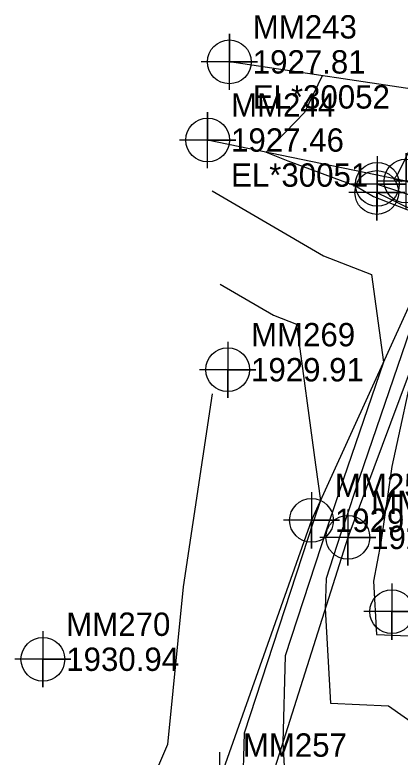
# Model space of a CAD drawing. Extents: x 1004378 to 1005103, y 553854 to 554288.
# Drawn here: x 1004938.6 to 1004979.8, y 554208.9 to 554288.4 of the extents above; entities that cross this region are included whole.
import ezdxf

# ---------------------------------------------------------------- set-up
doc = ezdxf.new("R2010")
doc.units = 0
for name, color, linetype in [('DTM Contours Major', 7, 'Continuous'), ('DTM Contours Minor', 7, 'Continuous'), ('Exist DTM Breakline', 7, 'Continuous'), ('Exist DTM Breakline Cogo Elevation', 7, 'Continuous'), ('Exist DTM Breakline Cogo Number', 7, 'Continuous'), ('Exist DTM Breakline Cogo Point CELL', 7, 'Continuous'), ('Exist DTM Regular Point CELL', 7, 'Continuous'), ('Exist DTM Regular Point Cogo Elevation', 7, 'Continuous'), ('Exist DTM Regular Point Cogo Number', 7, 'Continuous'), ('Exist Roads Soil', 7, 'Continuous'), ('Exist Roads Soil Cogo Comment', 7, 'Continuous'), ('Exist Roads Soil Cogo Elevation', 7, 'Continuous'), ('Exist Roads Soil Cogo Number', 7, 'Continuous'), ('Exist Roads Soil Cogo Point CELL', 7, 'Continuous')]:
    doc.layers.add(name, color=color, linetype=linetype)

msp = doc.modelspace()

# ---------------------------------------------------------------- linework, layer by layer
at = {"layer": 'DTM Contours Major'}
msp.add_lwpolyline([(1004959.718, 554247.837), (1004956.604, 554227.189), (1004954.914, 554210.3), (1004952.827, 554205.351), (1004957.486, 554203.505), (1004956.747, 554201.367), (1004957.928, 554197.612), (1004957.091, 554192.78), (1004956.399, 554184.65), (1004957.552, 554183.351), (1004960.987, 554182.443), (1004972.543, 554180.34), (1004973.586, 554164.908)], dxfattribs=at)
at = {"layer": 'DTM Contours Minor'}
for points in [[(1004971.499, 554281.9), (1004969.584, 554277.964), (1004965.483, 554273.724), (1004967.796, 554272.784), (1004975.049, 554270.111), (1004976.979, 554268.984), (1004983.286, 554266.522)], [(1004982.863, 554278.109), (1004979.529, 554271.254), (1004979.178, 554270.892), (1004979.965, 554270.572)], [(1004959.702, 554269.582), (1004971.624, 554262.617), (1004976.768, 554260.609), (1004978.047, 554251.242), (1004973.763, 554238.724), (1004972.987, 554236.396), (1004972.005, 554233.516), (1004967.53, 554219.799), (1004967.269, 554210.518), (1004967.445, 554207.322), (1004969.402, 554207.239), (1004978.487, 554200.785), (1004978.039, 554194.545), (1004976.925, 554192.516), (1004976.46, 554191.387), (1004975.325, 554186.125), (1004976.766, 554164.808), (1004977.29, 554160.519), (1004977.431, 554159.226), (1004977.764, 554154.77), (1004975.638, 554146.291), (1004977.602, 554126.359), (1004974.778, 554116.687)], [(1004984.509, 554265.252), (1004975.486, 554238.886), (1004973.8, 554233.83), (1004973.46, 554232.832), (1004971.91, 554228.081), (1004971.82, 554224.865), (1004972.377, 554214.703), (1004978.6, 554214.438), (1004982.901, 554211.383)], [(1004960.573, 554259.577), (1004966.268, 554256.25), (1004968.726, 554255.291), (1004970.783, 554240.224), (1004971.304, 554236.409), (1004970.551, 554234.199), (1004963.15, 554211.518), (1004962.971, 554205.136), (1004962.961, 554204.794), (1004962.243, 554202.716), (1004964.954, 554194.096), (1004969.359, 554191.452), (1004974.072, 554190.188), (1004973.609, 554188.041), (1004975.278, 554163.357), (1004975.678, 554160.081), (1004975.786, 554159.093), (1004976.151, 554154.202), (1004974.457, 554147.443), (1004976.568, 554126.021), (1004974.041, 554117.366)], [(1004981.55, 554252.068), (1004978.949, 554240.061), (1004977.774, 554231.939), (1004976.997, 554227.796), (1004977.31, 554222.084), (1004985.01, 554221.756)]]:
    msp.add_lwpolyline(points, dxfattribs=at)
at = {"layer": 'Exist DTM Breakline'}
for points in [[(1004977.38, 554270.285), (1004987.161, 554267.094), (1004974.231, 554232.47), (1004965.01, 554203.394)], [(1004977.332, 554269.403), (1004984.686, 554265.845), (1004970.343, 554234.297), (1004960.488, 554206.483)]]:
    msp.add_lwpolyline(points, dxfattribs=at)
at = {"layer": 'Exist DTM Breakline Cogo Point CELL'}
for points in [[(1004977.38, 554273.285), (1004977.38, 554267.285), (1004977.38, 554270.285), (1004980.38, 554270.285), (1004974.38, 554270.285)], [(1004977.332, 554272.403), (1004977.332, 554266.403), (1004977.332, 554269.403), (1004980.332, 554269.403), (1004974.332, 554269.403)], [(1004970.343, 554237.297), (1004970.343, 554231.297), (1004970.343, 554234.297), (1004973.343, 554234.297), (1004967.343, 554234.297)], [(1004974.231, 554235.47), (1004974.231, 554229.47), (1004974.231, 554232.47), (1004977.231, 554232.47), (1004971.231, 554232.47)], [(1004960.488, 554209.483), (1004960.488, 554203.483), (1004960.488, 554206.483), (1004963.488, 554206.483), (1004957.488, 554206.483)]]:
    msp.add_lwpolyline(points, dxfattribs=at)
for centre in [(1004977.38, 554270.285), (1004977.332, 554269.403), (1004970.343, 554234.297), (1004974.231, 554232.47)]:
    msp.add_circle(centre, 2.344, dxfattribs=at)
at = {"layer": 'Exist DTM Regular Point CELL'}
for points in [[(1004961.37, 554253.426), (1004961.37, 554247.426), (1004961.37, 554250.426), (1004964.37, 554250.426), (1004958.37, 554250.426)], [(1004978.936, 554227.517), (1004978.936, 554221.517), (1004978.936, 554224.517), (1004981.936, 554224.517), (1004975.936, 554224.517)], [(1004941.59, 554222.421), (1004941.59, 554216.421), (1004941.59, 554219.421), (1004944.59, 554219.421), (1004938.59, 554219.421)]]:
    msp.add_lwpolyline(points, dxfattribs=at)
for centre in [(1004961.37, 554250.426), (1004978.936, 554224.517), (1004941.59, 554219.421)]:
    msp.add_circle(centre, 2.344, dxfattribs=at)
at = {"layer": 'Exist Roads Soil'}
for points in [[(1005035.476, 554262.003), (1005019.749, 554266.277), (1004983.505, 554280.108), (1004961.55, 554283.385)], [(1005026.922, 554247.386), (1005013.881, 554254.375), (1004980.46, 554270.626), (1004959.228, 554275.018)]]:
    msp.add_lwpolyline(points, dxfattribs=at)
at = {"layer": 'Exist Roads Soil Cogo Point CELL'}
for points in [[(1004961.55, 554280.385), (1004961.55, 554286.385), (1004961.55, 554283.385), (1004964.55, 554283.385), (1004958.55, 554283.385)], [(1004959.228, 554272.018), (1004959.228, 554278.018), (1004959.228, 554275.018), (1004962.228, 554275.018), (1004956.228, 554275.018)], [(1004980.46, 554267.626), (1004980.46, 554273.626), (1004980.46, 554270.626), (1004983.46, 554270.626), (1004977.46, 554270.626)]]:
    msp.add_lwpolyline(points, dxfattribs=at)
for centre in [(1004961.55, 554283.385), (1004959.228, 554275.018), (1004980.46, 554270.626)]:
    msp.add_circle(centre, 2.344, dxfattribs=at)

# ---------------------------------------------------------------- texts
at = {"layer": 'Exist DTM Breakline Cogo Elevation'}
for s, p in [('1929.14', (1004972.843, 554233.047)), ('1926.47', (1004976.731, 554231.22))]:
    msp.add_text(s, height=2.5, dxfattribs=at).set_placement(p)
at = {"layer": 'Exist DTM Breakline Cogo Number'}
for s, p in [('MM254', (1004972.843, 554236.797)), ('MM252', (1004976.731, 554234.97)), ('MM257', (1004962.988, 554208.983))]:
    msp.add_text(s, height=2.5, dxfattribs=at).set_placement(p)
at = {"layer": 'Exist DTM Regular Point Cogo Elevation'}
for s, p in [('1929.91', (1004963.87, 554249.176)), ('1930.94', (1004944.09, 554218.171))]:
    msp.add_text(s, height=2.5, dxfattribs=at).set_placement(p)
at = {"layer": 'Exist DTM Regular Point Cogo Number'}
for s, p in [('MM269', (1004963.87, 554252.926)), ('MM270', (1004944.09, 554221.921))]:
    msp.add_text(s, height=2.5, dxfattribs=at).set_placement(p)
at = {"layer": 'Exist Roads Soil Cogo Comment'}
for s, p in [('EL*30052', (1004964.05, 554278.385)), ('EL*30051', (1004961.728, 554270.018))]:
    msp.add_text(s, height=2.5, dxfattribs=at).set_placement(p)
at = {"layer": 'Exist Roads Soil Cogo Elevation'}
for s, p in [('1927.81', (1004964.05, 554282.135)), ('1927.46', (1004961.728, 554273.768))]:
    msp.add_text(s, height=2.5, dxfattribs=at).set_placement(p)
at = {"layer": 'Exist Roads Soil Cogo Number'}
for s, p in [('MM243', (1004964.05, 554285.885)), ('MM244', (1004961.728, 554277.518))]:
    msp.add_text(s, height=2.5, dxfattribs=at).set_placement(p)

doc.saveas('drawing.dxf')
